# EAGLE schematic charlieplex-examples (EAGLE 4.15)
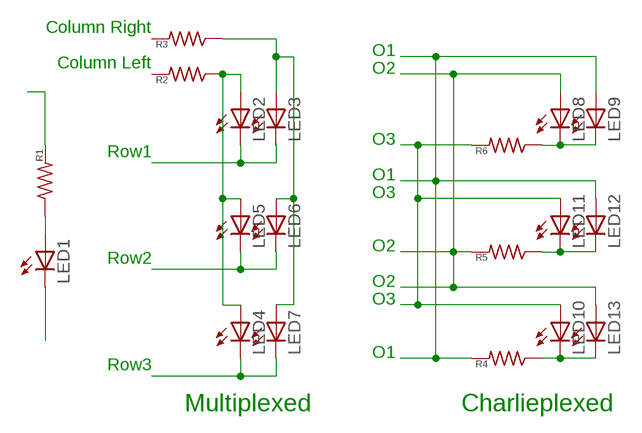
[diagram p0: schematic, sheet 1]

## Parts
LED1  LED5MM  [LED5MM]
LED2  LED5MM  [LED5MM]
LED3  LED5MM  [LED5MM]
LED4  LED5MM  [LED5MM]
LED5  LED5MM  [LED5MM]
LED6  LED5MM  [LED5MM]
LED7  LED5MM  [LED5MM]
LED8  LED5MM  [LED5MM]
LED9  LED5MM  [LED5MM]
LED10  LED5MM  [LED5MM]
LED11  LED5MM  [LED5MM]
LED12  LED5MM  [LED5MM]
LED13  LED5MM  [LED5MM]
R1  R-US_0207/10  [0207/10]
R2  R-US_0207/10  [0207/10]
R3  R-US_0207/10  [0207/10]
R4  R-US_0207/10  [0207/10]
R5  R-US_0207/10  [0207/10]
R6  R-US_0207/10  [0207/10]

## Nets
N$1: LED2.A LED4.A LED5.A R2.1
N$2: LED3.A LED6.A LED7.A R3.1
N$3: LED2.K(C) LED3.K(C)
N$4: LED5.K(C) LED6.K(C)
N$5: LED4.K(C) LED7.K(C)
N$6: LED10.A LED11.A R6.2
N$7: LED9.A LED12.A R4.2
N$8: LED8.K(C) LED9.K(C) R6.1
N$9: LED11.K(C) LED12.K(C) R5.1
N$10: LED10.K(C) LED13.K(C) R4.1
N$11: LED1.A R1.1
N$12: LED1.K(C)
N$13: R1.2
N$14: LED8.A LED13.A R5.2
Unconnected: R2.2 R3.2

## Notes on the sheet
- Column Right
- Column Left | O1
- O2
- Row1 | O3
- O1
- O3
- Row2 | O2
- O2
- O3
- Row3 | O1
- Multiplexed | Charlieplexed

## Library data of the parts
LED1-LED13 = led:LED: LED
R1-R6 = my-rcl:R-US_: RESISTOR, American symbol

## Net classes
0 default: width 0.6 mm
1 power: width 1 mm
